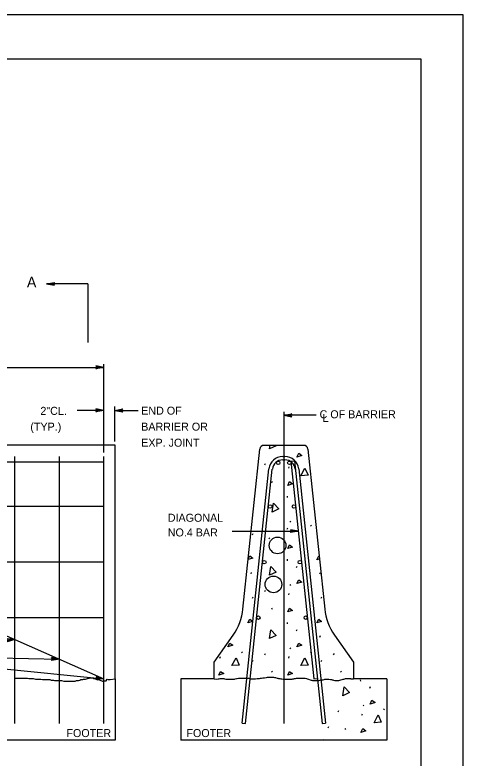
# Model space of a CAD drawing. Extents: x -111.7 to -103.2, y -200 to -189.
# Drawn here: x -106.59 to -103.23, y -194.55 to -188.99 of the extents above; entities that cross this region are included whole.
import ezdxf

# ---------------------------------------------------------------- set-up
doc = ezdxf.new("R2010")
doc.units = 0
for name, color, linetype in [('BORD-LINE', 7, 'Continuous'), ('CLIN', 7, 'Continuous'), ('DETL-PATT', 7, 'Continuous'), ('Level 10', 7, 'Continuous'), ('Level 12', 7, 'Continuous'), ('LGHT-UTIL_P', 7, 'Continuous'), ('SUBS-FOOT_P', 7, 'Continuous'), ('SUPR-PARA_P', 7, 'Continuous'), ('SUPR-RFRC', 7, 'Continuous'), ('USER-CLIP', 7, 'Continuous')]:
    doc.layers.add(name, color=color, linetype=linetype)

msp = doc.modelspace()

# ---------------------------------------------------------------- linework, layer by layer
at = {"layer": 'BORD-LINE'}
msp.add_lwpolyline([(-110.923, -189.3161), (-103.5488, -189.3161), (-103.5488, -199.6692), (-110.923, -199.6692)], close=True, dxfattribs=at)
at = {"layer": 'CLIN'}
msp.add_line((-104.5743, -191.9613), (-104.5743, -194.2947), dxfattribs=at)
at = {"layer": 'DETL-PATT'}
for p, q in [((-104.6805, -192.237), (-104.677, -192.2113)), ((-104.7166, -192.3581), (-104.7114, -192.3478)), ((-104.5375, -192.3826), (-104.5336, -192.3723)), ((-104.6663, -192.4818), (-104.6612, -192.4895)), ((-104.5504, -192.5913), (-104.5491, -192.6016)), ((-104.5285, -192.7807), (-104.5246, -192.7871)), ((-104.5483, -192.8404), (-104.5444, -192.8301)), ((-104.3752, -192.8103), (-104.37, -192.8168)), ((-104.8093, -192.8825), (-104.8042, -192.8721)), ((-104.6857, -192.9043), (-104.6806, -192.9121)), ((-104.5504, -193.0654), (-104.5491, -193.0757)), ((-104.3075, -193.0615), (-104.3275, -193.068)), ((-104.4783, -193.1272), (-104.4744, -193.1169)), ((-104.8196, -193.1736), (-104.8158, -193.1633)), ((-104.3043, -193.1736), (-104.3005, -193.1633)), ((-104.5285, -193.2548), (-104.5246, -193.2612)), ((-104.8093, -193.3565), (-104.8042, -193.3462)), ((-104.7166, -193.3063), (-104.7114, -193.296)), ((-104.5375, -193.3308), (-104.5336, -193.3205)), ((-104.294, -193.3565), (-104.2889, -193.3462)), ((-104.6663, -193.43), (-104.6612, -193.4377)), ((-104.5504, -193.5395), (-104.5491, -193.5498)), ((-104.4783, -193.6013), (-104.4744, -193.591)), ((-104.3043, -193.6477), (-104.3005, -193.6374)), ((-104.5285, -193.7288), (-104.5246, -193.7353)), ((-105.0528, -193.8048), (-105.0489, -193.7945)), ((-104.8905, -193.7585), (-104.8853, -193.7649)), ((-104.7166, -193.7804), (-104.7114, -193.77)), ((-104.5375, -193.8048), (-104.5336, -193.7945)), ((-104.3752, -193.7585), (-104.37, -193.7649)), ((-104.2013, -193.7804), (-104.1961, -193.77)), ((-104.8093, -193.8306), (-104.8042, -193.8203)), ((-104.294, -193.8306), (-104.2889, -193.8203)), ((-104.6663, -193.904), (-104.6612, -193.9118)), ((-104.151, -193.904), (-104.1459, -193.9118)), ((-104.002, -193.9677), (-104.0007, -193.9781)), ((-103.9298, -194.0296), (-103.926, -194.0193)), ((-103.9801, -194.1571), (-103.9762, -194.1636)), ((-104.1682, -194.2086), (-104.163, -194.1983)), ((-103.9891, -194.2331), (-103.9852, -194.2228)), ((-103.8268, -194.1867), (-103.8216, -194.1932)), ((-104.2422, -194.3285), (-104.2371, -194.3182)), ((-104.1179, -194.3323), (-104.1128, -194.34))]:
    msp.add_line(p, q, dxfattribs=at)
for points in [[(-104.6339, -192.2113), (-104.6316, -192.2139), (-104.6805, -192.237)], [(-104.477, -192.2989), (-104.4628, -192.2705), (-104.4396, -192.2873), (-104.477, -192.2989)], [(-104.4473, -192.4393), (-104.4164, -192.3813), (-104.3932, -192.4354), (-104.4473, -192.4393)], [(-104.5452, -192.5114), (-104.5324, -192.4831), (-104.5092, -192.4998), (-104.5452, -192.5114)], [(-104.6613, -192.7111), (-104.6523, -192.6454), (-104.6124, -192.6879), (-104.6613, -192.7111)], [(-104.5452, -192.9855), (-104.5324, -192.9572), (-104.5092, -192.9739), (-104.5452, -192.9855)], [(-104.8414, -193.0651), (-104.8287, -193.0396), (-104.8068, -193.0564), (-104.8417, -193.0676)], [(-104.3275, -193.068), (-104.3134, -193.0396), (-104.3095, -193.0425)], [(-104.6805, -193.1852), (-104.6715, -193.1195), (-104.6316, -193.162), (-104.6805, -193.1852)], [(-104.477, -193.247), (-104.4628, -193.2187), (-104.4396, -193.2354), (-104.477, -193.247)], [(-104.5452, -193.4596), (-104.5324, -193.4312), (-104.5092, -193.448), (-104.5452, -193.4596)], [(-104.8428, -193.542), (-104.8287, -193.5137), (-104.8068, -193.5304), (-104.8428, -193.542)], [(-104.3275, -193.542), (-104.3134, -193.5137), (-104.2915, -193.5304), (-104.3275, -193.542)], [(-104.6805, -193.6593), (-104.6715, -193.5936), (-104.6316, -193.6361), (-104.6805, -193.6593)], [(-104.9923, -193.7211), (-104.9781, -193.6928), (-104.9549, -193.7095), (-104.9923, -193.7211)], [(-104.477, -193.7211), (-104.4628, -193.6928), (-104.4396, -193.7095), (-104.477, -193.7211)], [(-104.9626, -193.8615), (-104.9317, -193.8035), (-104.9085, -193.8576), (-104.9626, -193.8615)], [(-104.4473, -193.8615), (-104.4164, -193.8035), (-104.3932, -193.8576), (-104.4473, -193.8615)], [(-105.0605, -193.9337), (-105.0477, -193.9053), (-105.0245, -193.9221), (-105.0605, -193.9337)], [(-104.5452, -193.9337), (-104.5324, -193.9053), (-104.5092, -193.9221), (-104.5452, -193.9337)], [(-104.1321, -194.0876), (-104.1231, -194.0219), (-104.0831, -194.0644), (-104.1321, -194.0876)], [(-103.9285, -194.1494), (-103.9144, -194.121), (-103.8912, -194.1378), (-103.9285, -194.1494)], [(-103.8989, -194.2898), (-103.868, -194.2318), (-103.8448, -194.2859), (-103.8989, -194.2898)], [(-103.9968, -194.3619), (-103.9839, -194.3336), (-103.9608, -194.3504), (-103.9968, -194.3619)], [(-104.282, -194.4197), (-104.2802, -194.4161), (-104.2755, -194.4197)]]:
    msp.add_lwpolyline(points, dxfattribs=at)
at = {"layer": 'Level 10'}
for p, q in [((-106.3499, -191.0012), (-106.2902, -190.9907)), ((-106.0419, -191.0012), (-106.3499, -191.0012)), ((-106.3499, -191.0012), (-106.2902, -191.0117)), ((-106.3016, -191.0012), (-106.2902, -190.9907)), ((-106.2902, -191.0117), (-106.3016, -191.0012)), ((-106.0419, -191.0012), (-106.0419, -191.4407)), ((-105.9211, -191.627), (-105.9807, -191.6165)), ((-105.9807, -191.6165), (-105.9694, -191.627)), ((-105.9211, -192.2652), (-105.9211, -191.602)), ((-109.5877, -191.627), (-105.9211, -191.627)), ((-105.9211, -191.627), (-105.9807, -191.6375)), ((-105.9694, -191.627), (-105.9807, -191.6375)), ((-105.9211, -191.9492), (-106.1209, -191.9492)), ((-105.9211, -191.9492), (-105.9807, -191.9387)), ((-105.9807, -191.9387), (-105.9694, -191.9492)), ((-105.9211, -191.9492), (-105.9807, -191.9597)), ((-105.9694, -191.9492), (-105.9807, -191.9597)), ((-105.8396, -192.1818), (-105.8396, -191.9216)), ((-105.8396, -191.9492), (-105.7801, -191.9387)), ((-105.8396, -191.9492), (-105.6644, -191.9492)), ((-105.8396, -191.9492), (-105.7801, -191.9597)), ((-105.7912, -191.9492), (-105.7801, -191.9387)), ((-105.7801, -191.9597), (-105.7912, -191.9492)), ((-104.5743, -191.9863), (-104.5146, -191.9758)), ((-104.3333, -191.9863), (-104.5743, -191.9863)), ((-104.5743, -191.9863), (-104.5146, -191.9968)), ((-104.526, -191.9863), (-104.5146, -191.9758)), ((-104.5146, -191.9968), (-104.526, -191.9863)), ((-104.4656, -192.8538), (-104.5253, -192.8433)), ((-104.5253, -192.8433), (-104.5139, -192.8538)), ((-104.9619, -192.8538), (-104.4656, -192.8538)), ((-104.4656, -192.8538), (-104.5253, -192.8643)), ((-104.5139, -192.8538), (-104.5253, -192.8643)), ((-107.6859, -193.7857), (-106.5877, -193.6659)), ((-106.5877, -193.6659), (-106.648, -193.662)), ((-106.5877, -193.6659), (-106.6457, -193.6828)), ((-107.6859, -193.7857), (-106.2544, -193.8136)), ((-107.6859, -193.7857), (-105.9211, -193.9613)), ((-106.3027, -193.8127), (-106.3141, -193.823)), ((-106.2544, -193.8136), (-106.3141, -193.823)), ((-106.2544, -193.8136), (-106.3137, -193.802)), ((-106.3137, -193.802), (-106.3027, -193.8127)), ((-105.9691, -193.9565), (-105.9813, -193.9659)), ((-105.9211, -193.9613), (-105.9813, -193.9659)), ((-105.9211, -193.9613), (-105.9793, -193.9451)), ((-105.9793, -193.9451), (-105.9691, -193.9565))]:
    msp.add_line(p, q, dxfattribs=at)
for points in [[(-106.2902, -191.0117), (-106.3499, -191.0012), (-106.2902, -190.9907), (-106.3016, -191.0012)], [(-105.9807, -191.6165), (-105.9211, -191.627), (-105.9807, -191.6375), (-105.9694, -191.627)], [(-105.9807, -191.9387), (-105.9211, -191.9492), (-105.9807, -191.9597), (-105.9694, -191.9492)], [(-105.7801, -191.9597), (-105.8396, -191.9492), (-105.7801, -191.9387), (-105.7912, -191.9492)], [(-104.5146, -191.9968), (-104.5743, -191.9863), (-104.5146, -191.9758), (-104.526, -191.9863)], [(-104.5253, -192.8433), (-104.4656, -192.8538), (-104.5253, -192.8643), (-104.5139, -192.8538)], [(-106.648, -193.662), (-106.5877, -193.6659), (-106.6457, -193.6828), (-106.6357, -193.6711)], [(-106.3137, -193.802), (-106.2544, -193.8136), (-106.3141, -193.823), (-106.3027, -193.8127)], [(-105.9793, -193.9451), (-105.9211, -193.9613), (-105.9813, -193.9659), (-105.9691, -193.9565)]]:
    msp.add_lwpolyline(points, close=True, dxfattribs=at)
at = {"layer": 'LGHT-UTIL_P'}
for centre in [(-104.621, -192.9613), (-104.6517, -193.253)]:
    msp.add_circle(centre, 0.0625, dxfattribs=at)
at = {"layer": 'SUBS-FOOT_P'}
for p, q in [((-105.8377, -193.9613), (-105.8377, -194.4197)), ((-105.3451, -193.9613), (-105.3451, -194.4197)), ((-105.0951, -193.9613), (-105.3451, -193.9613)), ((-103.8035, -193.9613), (-104.0535, -193.9613)), ((-103.8035, -193.9613), (-103.8035, -194.4197)), ((-105.8377, -194.4197), (-110.4191, -194.4197)), ((-103.8035, -194.4197), (-105.3451, -194.4197))]:
    msp.add_line(p, q, dxfattribs=at)
for points in [[(-106.5886, -193.956), (-106.578, -193.956), (-106.5604, -193.956), (-106.5427, -193.956), (-106.5286, -193.956), (-106.5144, -193.956), (-106.5074, -193.956), (-106.5003, -193.956), (-106.4932, -193.956), (-106.4826, -193.9595), (-106.4685, -193.9595), (-106.4508, -193.9595), (-106.4332, -193.9631), (-106.4226, -193.9631), (-106.4155, -193.9631), (-106.4084, -193.9631), (-106.4014, -193.9631), (-106.3943, -193.9631), (-106.3802, -193.9666), (-106.3696, -193.9666), (-106.3625, -193.9666), (-106.3484, -193.9666), (-106.3413, -193.9666), (-106.3272, -193.9666), (-106.3166, -193.9701), (-106.306, -193.9701), (-106.2989, -193.9701), (-106.2918, -193.9737), (-106.2848, -193.9737), (-106.2777, -193.9737), (-106.2671, -193.9737), (-106.26, -193.9737), (-106.2459, -193.9737), (-106.2388, -193.9737), (-106.2212, -193.9772), (-106.2106, -193.9772), (-106.2, -193.9772), (-106.1894, -193.9772), (-106.1788, -193.9772), (-106.1717, -193.9772), (-106.1647, -193.9772), (-106.1505, -193.9772), (-106.1435, -193.9772), (-106.1364, -193.9772), (-106.1258, -193.9737), (-106.1187, -193.9737), (-106.1117, -193.9737), (-106.1011, -193.9701), (-106.094, -193.9666), (-106.0869, -193.9666), (-106.0799, -193.9666), (-106.0728, -193.9631), (-106.0587, -193.9631), (-106.0445, -193.9595), (-106.0304, -193.956), (-106.0127, -193.9525), (-106.0037, -193.9545), (-105.996, -193.9571), (-105.9866, -193.9585), (-105.9837, -193.9607), (-105.9767, -193.962), (-105.9691, -193.9683), (-105.9579, -193.9662), (-105.9501, -193.9713), (-105.9442, -193.973), (-105.9362, -193.9758), (-105.9255, -193.9808), (-105.9139, -193.9763), (-105.9032, -193.9756), (-105.8961, -193.9631), (-105.8891, -193.9666), (-105.882, -193.9666), (-105.8749, -193.9666), (-105.8377, -193.9613)], [(-105.0951, -193.9613), (-105.0756, -193.9632), (-105.0652, -193.9611), (-105.0579, -193.9601), (-105.0496, -193.959), (-105.0434, -193.959), (-105.0371, -193.958), (-105.0319, -193.958), (-105.0226, -193.958), (-105.0174, -193.9601), (-105.0091, -193.9622), (-105.0018, -193.9632), (-104.9924, -193.9642), (-104.9862, -193.9642), (-104.9799, -193.9642), (-104.9716, -193.9642), (-104.9654, -193.9632), (-104.9581, -193.9632), (-104.9508, -193.9632), (-104.9446, -193.9622), (-104.9373, -193.9601), (-104.929, -193.959), (-104.9238, -193.958), (-104.9144, -193.957), (-104.905, -193.9559), (-104.8946, -193.9559), (-104.8853, -193.9559), (-104.8717, -193.9549), (-104.8645, -193.9549), (-104.8582, -193.9549), (-104.8489, -193.9549), (-104.8437, -193.9559), (-104.8385, -193.957), (-104.8312, -193.959), (-104.8218, -193.9601), (-104.8145, -193.9601), (-104.8052, -193.9601), (-104.7958, -193.9601), (-104.7864, -193.9601), (-104.775, -193.959), (-104.7646, -193.958), (-104.7573, -193.958), (-104.749, -193.957), (-104.7407, -193.9549), (-104.7303, -193.9538), (-104.7199, -193.9528), (-104.7043, -193.9497), (-104.697, -193.9486), (-104.6907, -193.9476), (-104.6814, -193.9476), (-104.671, -193.9476), (-104.6658, -193.9476), (-104.6595, -193.9476), (-104.6512, -193.9486), (-104.6439, -193.9507), (-104.6356, -193.9518), (-104.6252, -193.9549), (-104.62, -193.9559), (-104.6138, -193.958), (-104.6044, -193.959), (-104.5971, -193.9601), (-104.5888, -193.9611), (-104.5794, -193.9622), (-104.569, -193.9622), (-104.5576, -193.9632), (-104.5461, -193.9632), (-104.5378, -193.9632), (-104.5243, -193.9632), (-104.517, -193.9632), (-104.5118, -193.9622), (-104.5056, -193.9601), (-104.4993, -193.9601), (-104.4941, -193.959), (-104.4869, -193.958), (-104.4796, -193.957), (-104.4723, -193.957), (-104.4619, -193.9559), (-104.4525, -193.9549), (-104.4432, -193.9549), (-104.4317, -193.9549), (-104.4255, -193.9549), (-104.4203, -193.9549), (-104.414, -193.9549), (-104.4057, -193.958), (-104.3984, -193.9611), (-104.3891, -193.9642), (-104.3766, -193.9695), (-104.3703, -193.9715), (-104.3651, -193.9715), (-104.3599, -193.9726), (-104.3547, -193.9736), (-104.3485, -193.9736), (-104.3423, -193.9736), (-104.336, -193.9736), (-104.3308, -193.9736), (-104.3246, -193.9726), (-104.3183, -193.9726), (-104.3121, -193.9726), (-104.3017, -193.9705), (-104.2944, -193.9695), (-104.2861, -193.9684), (-104.2798, -193.9674), (-104.2715, -193.9653), (-104.2663, -193.9642), (-104.258, -193.9642), (-104.2528, -193.9642), (-104.2466, -193.9642), (-104.2372, -193.9642), (-104.2247, -193.9653), (-104.2185, -193.9653), (-104.2133, -193.9674), (-104.2081, -193.9695), (-104.2018, -193.9715), (-104.1925, -193.9726), (-104.1862, -193.9726), (-104.1748, -193.9726), (-104.1696, -193.9726), (-104.1623, -193.9726), (-104.155, -193.9705), (-104.1467, -193.9674), (-104.1373, -193.9653), (-104.1311, -193.9642), (-104.1248, -193.9622), (-104.1186, -193.9601), (-104.1134, -193.959), (-104.1082, -193.958), (-104.102, -193.958), (-104.0947, -193.958), (-104.0895, -193.958), (-104.0843, -193.958), (-104.0791, -193.958), (-104.0739, -193.959), (-104.0716, -193.9598), (-104.0656, -193.9607), (-104.0587, -193.96), (-104.0535, -193.9613)]]:
    msp.add_lwpolyline(points, dxfattribs=at)
at = {"layer": 'SUPR-PARA_P'}
for p, q in [((-105.8377, -192.2113), (-110.4191, -192.2113)), ((-105.8377, -193.9613), (-105.8377, -192.2113)), ((-105.0951, -193.9613), (-105.0951, -193.8363)), ((-104.0535, -193.8363), (-104.0535, -193.9613))]:
    msp.add_line(p, q, dxfattribs=at)
for points in [[(-104.7232, -192.2113), (-104.4253, -192.2113)], [(-104.8808, -193.4381), (-104.7543, -192.2393)], [(-104.3942, -192.2393), (-104.2678, -193.4381)], [(-105.0951, -193.8363), (-104.9532, -193.6326)], [(-104.1954, -193.6326), (-104.0535, -193.8363)]]:
    msp.add_lwpolyline(points, dxfattribs=at)
for centre, radius, start, end in [((-104.7232, -192.2426), 0.0312, 90, 173.9793), ((-104.4253, -192.2426), 0.0312, 6.0207, 90), ((-105.2951, -193.3944), 0.4167, 325.1455, 353.9793), ((-103.8534, -193.3944), 0.4167, 186.0207, 214.8545)]:
    msp.add_arc(centre, radius, start, end, dxfattribs=at)
at = {"layer": 'SUPR-RFRC'}
for p, q in [((-105.9211, -192.3363), (-110.4191, -192.3363)), ((-109.5877, -192.3363), (-105.9211, -193.9613)), ((-106.5877, -194.2947), (-106.5877, -192.2947)), ((-106.2544, -194.2947), (-106.2544, -192.2947)), ((-105.9211, -194.2947), (-105.9211, -192.2947)), ((-104.5826, -192.2947), (-104.566, -192.2947)), ((-104.5826, -192.3207), (-104.566, -192.3207)), ((-104.5207, -192.3312), (-104.4948, -192.3285)), ((-104.5207, -192.3312), (-104.3488, -193.9613)), ((-104.4948, -192.3285), (-104.2875, -194.2947)), ((-104.887, -194.2919), (-104.6862, -192.3879)), ((-104.8611, -194.2947), (-104.6603, -192.3906)), ((-104.4624, -192.3879), (-104.2616, -194.2919)), ((-105.9211, -192.6697), (-110.4191, -192.6697)), ((-105.9211, -193.0863), (-110.4191, -193.0863)), ((-105.9211, -193.503), (-110.4191, -193.503)), ((-104.3488, -193.9613), (-104.3229, -193.9586)), ((-104.887, -194.2919), (-104.8611, -194.2947)), ((-104.2875, -194.2947), (-104.2616, -194.2919))]:
    msp.add_line(p, q, dxfattribs=at)
for centre in [(-104.616, -192.3429), (-104.5326, -192.3429), (-104.6766, -192.6697), (-104.4981, -192.6697), (-104.7206, -193.0863), (-104.4542, -193.0863), (-104.7645, -193.503), (-104.4102, -193.503)]:
    msp.add_circle(centre, 0.013, dxfattribs=at)
for centre, radius, start, end in [((-104.5826, -192.3988), 0.1042, 90, 173.9793), ((-104.5826, -192.3988), 0.0781, 90, 173.9793), ((-104.566, -192.3988), 0.1042, 6.0207, 90), ((-104.566, -192.3988), 0.0781, 6.0207, 90)]:
    msp.add_arc(centre, radius, start, end, dxfattribs=at)
at = {"layer": 'USER-CLIP'}
msp.add_lwpolyline([(-103.2319, -188.9861), (-111.7319, -188.9861), (-111.7319, -199.9861), (-103.2319, -199.9861)], close=True, dxfattribs=at)

# ---------------------------------------------------------------- texts
at = {"layer": 'Level 12'}
for s, height, p in [('A', 0.08, (-106.4979, -191.0286)), ('END OF', 0.06, (-105.642, -191.9816)), ('C OF BARRIER', 0.06, (-104.3065, -192.0087)), ('L', 0.06, (-104.284, -192.0355)), ('(TYP.)', 0.06, (-106.472, -192.1016)), ('BARRIER OR', 0.06, (-105.642, -192.1016)), ('EXP. JOINT', 0.06, (-105.642, -192.2216)), ('DIAGONAL', 0.06, (-105.443, -192.784)), ('NO.4 BAR', 0.06, (-105.443, -192.894)), ('FOOTER', 0.06, (-106.2017, -194.3972)), ('FOOTER', 0.06, (-105.3034, -194.3972))]:
    msp.add_text(s, height=height, dxfattribs=at).set_placement(p)
msp.add_text('2"CL.', height=0.06, rotation=360, dxfattribs=at).set_placement((-106.3967, -191.983))

doc.saveas('drawing.dxf')
